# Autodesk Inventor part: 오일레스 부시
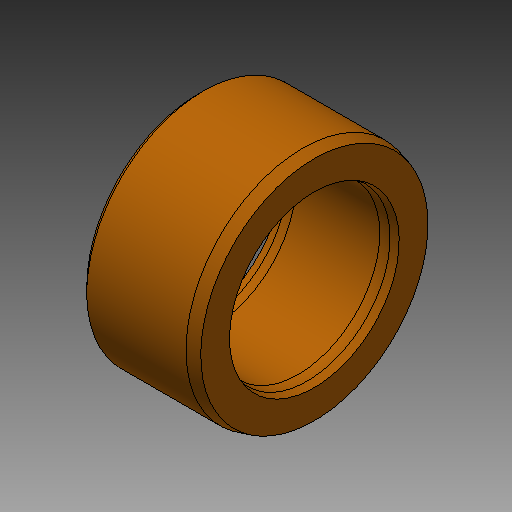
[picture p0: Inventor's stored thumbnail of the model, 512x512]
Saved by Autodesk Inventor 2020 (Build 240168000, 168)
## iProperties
Created: 2024-02
Part Number: 오일레스 부시
Material: 강철, 합금
Document SubType Name: Modeling
Designer: mdu-01
Density: 1 g/cm^3
Appearance: 주황색
Author: mdu-01
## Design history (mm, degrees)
sketch "스케치1"
  geometry: L1 (0, 0)-(10, 0); L2 (1.395, 7)-(8.605, 7); L3 (10, 7.268)-(10, 9.732); L4 (9, 10)-(0.5, 10); L5 (0, 9.5)-(0, 7.268); L6 (9, 10)-(10, 9.732); L7 (9.381, 7.102)-(10, 7.268); L8 (0.619, 7.102)-(0, 7.268); L9 (0.5, 10)-(0, 9.5); A1 r 3 centre (1.395, 10) between (0.619, 7.102) and (1.395, 7); A2 r 3 centre (8.605, 10) between (8.605, 7) and (9.381, 7.102); 6 further points
  constraints: 18 end point, 14 point on line, 4 point on circle, 4 tangent, 2 centre point, 2 horizontal, 2 parallel, 1 equal radius, 1 perpendicular
  dimensions: "d0" = 10 distance of L1.start L1.end; "d1" = 14 diameter of L2 L1; "d2" = 20 diameter of L4 L1; "d3" = 1 distance of L4.start point (10, 10); "d4" = 15 deg angle of L4 L6; "d5" = 1 distance of point (9, 7) point (10, 7) (= d3); "d6" = 15 deg angle of L2 L7 (= d4); "d7" = 1 distance of point (1, 7) point (0, 7) (= d3); "d8" = 15 deg angle of L2 L8 (= d4); "d9" = 3 radius of A1; "d10" = 0.5 distance of L4.end point (0, 10); "d11" = 0.5 distance of L5.start point (0, 10) (= d10)
revolve "회전1" sketch "스케치1" stored, may be unused: angle "d12" = 90 deg
node "솔리드1"
